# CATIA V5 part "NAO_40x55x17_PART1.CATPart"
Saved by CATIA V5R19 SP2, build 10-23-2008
Part number: NAO_40x55x17_PART1
Bounding box of the stored display mesh (mm): x 0 to 17, y -22.494 to 22.494, z -22.494 to 22.494
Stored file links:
  G:\EU_thinkMotion\CFAO_2010\MMS_groupe2\MMS_groupe2\OK\nrosalie\nrosalie_cfao_support_d_arme_legere_final\NAO_40x55x17_PART1.CATPart
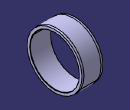
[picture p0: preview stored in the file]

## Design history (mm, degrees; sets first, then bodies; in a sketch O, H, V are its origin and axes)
Set1
  Point1: (0, 0, 0)
  Point2: (1, 0, 0)
  Point3: (0, 1, 0)
  Plane1: type 3Points, Element1 Point1, Element2 Point2, Element3 Point3
Body1 (main body)
  Sketch1 on Plane1, origin (0, 0, 0), H (1, 0, 0), V (0, 1, 0)
    arc A1 centre (0.3, 20.3) radius 0.3 from (0, 20.3) to (0.3, 20) ccw
    point P1 (0.3, 20)
    point P2 (16.7, 20)
    line L1 (0.3, 20) -> (16.7, 20)
    arc A2 centre (16.7, 20.3) radius 0.3 from (16.7, 20) to (17, 20.3) ccw
    point P3 (17, 20.3)
    point P4 (17, 22.35)
    line L2 (17, 20.3) -> (17, 22.35)
    point P5 (17, 22.35)
    point P6 (15.4, 22.5)
    line L3 (17, 22.35) -> (15.4, 22.5)
    point P7 (15.4, 22.5)
    point P8 (1.6, 22.5)
    line L4 (15.4, 22.5) -> (1.6, 22.5)
    point P9 (1.6, 22.5)
    point P10 (0, 22.35)
    line L5 (1.6, 22.5) -> (0, 22.35)
    point P11 (0, 22.35)
    point P12 (0, 20.3)
    line L6 (0, 22.35) -> (0, 20.3)
    point P13 (17, 0)
    point P14 (0, 0)
    axis line L7 (17, 0) -> (0, 0)
    point P15 (0, 20.3)
    point P16 (0.3, 20)
    point P17 (0.3, 20)
    point P18 (16.7, 20)
    point P19 (16.7, 20)
    point P20 (17, 20.3)
    point P21 (17, 20.3)
    point P22 (17, 22.35)
    point P23 (17, 22.35)
    point P24 (15.4, 22.5)
    point P25 (15.4, 22.5)
    point P26 (1.6, 22.5)
    point P27 (1.6, 22.5)
    point P28 (0, 22.35)
    point P29 (0, 22.35)
    point P30 (0, 20.3)
    coincidence: P15 P30, P16 P17, P18 P19, P20 P21, P22 P23, P24 P25, P26 P27, P28 P29
  Shaft1: profile Sketch1, axis Sketch1.L7, angle 0, second angle 360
